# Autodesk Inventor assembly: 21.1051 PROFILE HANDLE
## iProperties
Created: 2007-02
Part Number: 21.1051 PROFILE HANDLE
Document SubType Name: Assembly
Designer: Andy Moles
Mass: 501.818 g
Surface Area: 1411.22 cm^2
Volume: 161.836 cm^3
Density: 3.10078 g/cm^3
Author: Andy Moles
